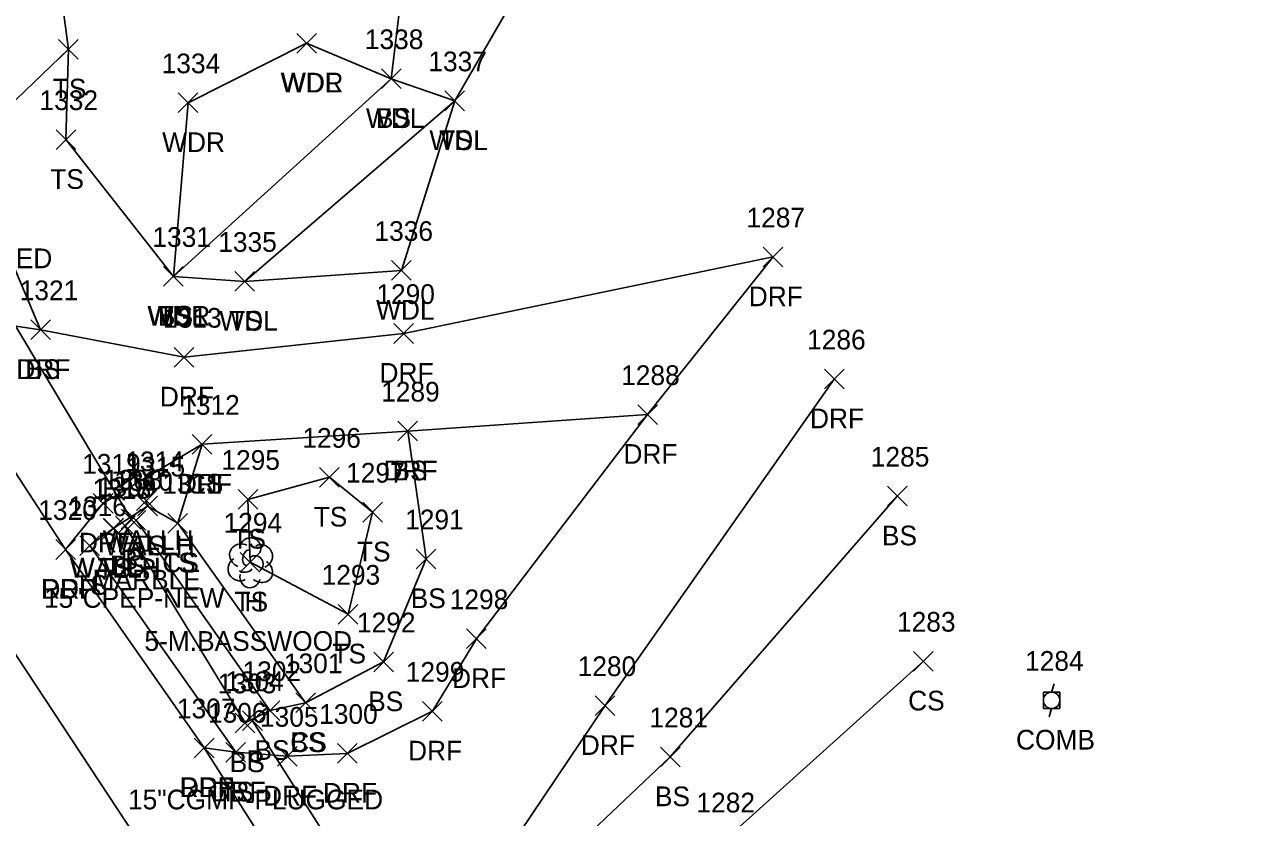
# Model space of a CAD drawing. Extents: x 1501299 to 1502485, y 381423 to 383765.
# Drawn here: x 1501750.2 to 1501874.8, y 383089.7 to 383170.2 of the extents above; entities that cross this region are included whole.
import ezdxf

# ---------------------------------------------------------------- set-up
doc = ezdxf.new("R2010")
doc.units = 0
for name, color, linetype in [('D_A', 7, 'Continuous'), ('D_C', 7, 'Continuous'), ('D_I', 7, 'Continuous'), ('D_TIC', 7, 'Continuous'), ('DCP', 7, 'Continuous'), ('DHW', 7, 'Continuous'), ('L_A', 7, 'Continuous'), ('L_C', 7, 'Continuous'), ('L_I', 7, 'Continuous'), ('L_TIC', 7, 'Continuous'), ('LAWA', 7, 'Continuous'), ('LELB', 7, 'Continuous'), ('LTD', 7, 'Continuous'), ('P_A', 7, 'Continuous'), ('P_I', 7, 'Continuous'), ('P_TIC', 7, 'Continuous'), ('PET', 7, 'Continuous'), ('PRC', 7, 'Continuous'), ('R_A', 7, 'Continuous'), ('R_I', 7, 'Continuous'), ('R_TIC', 7, 'Continuous'), ('RDF', 7, 'Continuous'), ('U_A', 7, 'Continuous'), ('U_I', 7, 'Continuous'), ('UP', 7, 'Continuous')]:
    doc.layers.add(name, color=color, linetype=linetype)

msp = doc.modelspace()

# ---------------------------------------------------------------- linework, layer by layer
at = {"layer": 'D_TIC'}
for points in [[(1501761.59, 383120.84), (1501763.59, 383122.84)], [(1501763.59, 383120.84), (1501761.59, 383122.84)], [(1501761.73, 383120.3), (1501763.73, 383122.3)], [(1501763.73, 383120.3), (1501761.73, 383122.3)], [(1501760.06, 383118.97), (1501762.06, 383120.97)], [(1501762.06, 383118.97), (1501760.06, 383120.97)], [(1501758.24, 383118.02), (1501760.24, 383120.02)], [(1501760.24, 383118.02), (1501758.24, 383120.02)], [(1501758.27, 383118.07), (1501760.27, 383120.07)], [(1501760.27, 383118.07), (1501758.27, 383120.07)], [(1501772.39, 383098.51), (1501774.39, 383100.51)], [(1501774.39, 383098.51), (1501772.39, 383100.51)]]:
    msp.add_lwpolyline(points, dxfattribs=at)
at = {"layer": 'DCP'}
for points in [[(1501761.06, 383119.97), (1501740.36, 383154.45)], [(1501794, 383067.07), (1501773.39, 383099.51)]]:
    msp.add_lwpolyline(points, dxfattribs=at)
at = {"layer": 'DHW'}
msp.add_lwpolyline([(1501762.59, 383121.84), (1501762.73, 383121.3), (1501759.24, 383119.02), (1501759.27, 383119.07)], dxfattribs=at)
at = {"layer": 'L_TIC'}
for points in [[(1501753.69, 383166.68), (1501755.69, 383168.68)], [(1501755.69, 383166.68), (1501753.69, 383168.68)], [(1501753.69, 383166.68), (1501755.69, 383168.68)], [(1501755.69, 383166.68), (1501753.69, 383168.68)], [(1501777.88, 383167.29), (1501779.88, 383169.29)], [(1501779.88, 383167.29), (1501777.88, 383169.29)], [(1501777.88, 383167.29), (1501779.88, 383169.29)], [(1501779.88, 383167.29), (1501777.88, 383169.29)], [(1501786.49, 383163.69), (1501788.49, 383165.69)], [(1501788.49, 383163.69), (1501786.49, 383165.69)], [(1501786.49, 383163.69), (1501788.49, 383165.69)], [(1501788.49, 383163.69), (1501786.49, 383165.69)], [(1501765.85, 383161.24), (1501767.85, 383163.24)], [(1501767.85, 383161.24), (1501765.85, 383163.24)], [(1501792.94, 383161.44), (1501794.94, 383163.44)], [(1501794.94, 383161.44), (1501792.94, 383163.44)], [(1501792.94, 383161.44), (1501794.94, 383163.44)], [(1501794.94, 383161.44), (1501792.94, 383163.44)], [(1501753.44, 383157.5), (1501755.44, 383159.5)], [(1501755.44, 383157.5), (1501753.44, 383159.5)], [(1501787.52, 383144.22), (1501789.52, 383146.22)], [(1501789.52, 383144.22), (1501787.52, 383146.22)], [(1501764.35, 383143.61), (1501766.35, 383145.61)], [(1501766.35, 383143.61), (1501764.35, 383145.61)], [(1501764.35, 383143.61), (1501766.35, 383145.61)], [(1501766.35, 383143.61), (1501764.35, 383145.61)], [(1501764.35, 383143.61), (1501766.35, 383145.61)], [(1501766.35, 383143.61), (1501764.35, 383145.61)], [(1501764.35, 383143.61), (1501766.35, 383145.61)], [(1501766.35, 383143.61), (1501764.35, 383145.61)], [(1501771.6, 383143.11), (1501773.6, 383145.11)], [(1501773.6, 383143.11), (1501771.6, 383145.11)], [(1501771.6, 383143.11), (1501773.6, 383145.11)], [(1501773.6, 383143.11), (1501771.6, 383145.11)], [(1501750.87, 383138.2), (1501752.87, 383140.2)], [(1501752.87, 383138.2), (1501750.87, 383140.2)], [(1501788.16, 383127.91), (1501790.16, 383129.91)], [(1501790.16, 383127.91), (1501788.16, 383129.91)], [(1501767.27, 383126.57), (1501769.27, 383128.57)], [(1501769.27, 383126.57), (1501767.27, 383128.57)], [(1501780.2, 383123.22), (1501782.2, 383125.22)], [(1501782.2, 383123.22), (1501780.2, 383125.22)], [(1501761.73, 383120.3), (1501763.73, 383122.3)], [(1501763.73, 383120.3), (1501761.73, 383122.3)], [(1501771.92, 383120.98), (1501773.92, 383122.98)], [(1501773.92, 383120.98), (1501771.92, 383122.98)], [(1501837.89, 383121.31), (1501839.89, 383123.31)], [(1501839.89, 383121.31), (1501837.89, 383123.31)], [(1501784.59, 383119.68), (1501786.59, 383121.68)], [(1501786.59, 383119.68), (1501784.59, 383121.68)], [(1501784.59, 383119.68), (1501786.59, 383121.68)], [(1501786.59, 383119.68), (1501784.59, 383121.68)], [(1501758.24, 383118.02), (1501760.24, 383120.02)], [(1501760.24, 383118.02), (1501758.24, 383120.02)], [(1501759.46, 383118.27), (1501761.46, 383120.27)], [(1501761.46, 383118.27), (1501759.46, 383120.27)], [(1501760.56, 383118.86), (1501762.56, 383120.86)], [(1501762.56, 383118.86), (1501760.56, 383120.86)], [(1501764.79, 383118.56), (1501766.79, 383120.56)], [(1501766.79, 383118.56), (1501764.79, 383120.56)], [(1501764.79, 383118.56), (1501766.79, 383120.56)], [(1501766.79, 383118.56), (1501764.79, 383120.56)], [(1501755.86, 383116.28), (1501757.86, 383118.28)], [(1501757.86, 383116.28), (1501755.86, 383118.28)], [(1501772.15, 383114.6), (1501774.15, 383116.6)], [(1501774.15, 383114.6), (1501772.15, 383116.6)], [(1501790.02, 383114.94), (1501792.02, 383116.94)], [(1501792.02, 383114.94), (1501790.02, 383116.94)], [(1501782.1, 383109.32), (1501784.1, 383111.32)], [(1501784.1, 383109.32), (1501782.1, 383111.32)], [(1501782.1, 383109.32), (1501784.1, 383111.32)], [(1501784.1, 383109.32), (1501782.1, 383111.32)], [(1501785.7, 383104.48), (1501787.7, 383106.48)], [(1501787.7, 383104.48), (1501785.7, 383106.48)], [(1501840.55, 383104.55), (1501842.55, 383106.55)], [(1501842.55, 383104.55), (1501840.55, 383106.55)], [(1501777.79, 383100.33), (1501779.79, 383102.33)], [(1501779.79, 383100.33), (1501777.79, 383102.33)], [(1501777.79, 383100.33), (1501779.79, 383102.33)], [(1501779.79, 383100.33), (1501777.79, 383102.33)], [(1501774.15, 383099.53), (1501776.15, 383101.53)], [(1501776.15, 383099.53), (1501774.15, 383101.53)], [(1501774.15, 383099.53), (1501776.15, 383101.53)], [(1501776.15, 383099.53), (1501774.15, 383101.53)], [(1501771.63, 383098.29), (1501773.63, 383100.29)], [(1501773.63, 383098.29), (1501771.63, 383100.29)], [(1501770.69, 383095.31), (1501772.69, 383097.31)], [(1501772.69, 383095.31), (1501770.69, 383097.31)], [(1501814.83, 383094.83), (1501816.83, 383096.83)], [(1501816.83, 383094.83), (1501814.83, 383096.83)]]:
    msp.add_lwpolyline(points, dxfattribs=at)
at = {"layer": 'LAWA'}
for points in [[(1501765.35, 383144.61), (1501766.85, 383162.24), (1501778.88, 383168.29)], [(1501765.35, 383144.61), (1501772.6, 383144.11), (1501788.52, 383145.22), (1501793.94, 383162.44), (1501787.49, 383164.69), (1501778.88, 383168.29)]]:
    msp.add_lwpolyline(points, dxfattribs=at)
at = {"layer": 'LELB'}
for points in [[(1501744.07, 383157.49), (1501754.69, 383167.68), (1501752.78, 383182.05), (1501755.19, 383195.99), (1501761.59, 383208.77), (1501771, 383222.88), (1501783.3, 383233.77), (1501801.07, 383247.03), (1501816.32, 383251.23)], [(1501772.6, 383144.11), (1501793.94, 383162.44), (1501805.51, 383182.49), (1501797.96, 383202.01), (1501788.35, 383224.29)], [(1501765.35, 383144.61), (1501787.49, 383164.69), (1501789.31, 383179.79), (1501788.17, 383200.21), (1501778.27, 383209.23)], [(1501765.35, 383144.61), (1501754.44, 383158.5), (1501754.69, 383167.68)], [(1501751.87, 383139.2), (1501744.39, 383156.78)], [(1501789.16, 383128.91), (1501791.02, 383115.94), (1501786.7, 383105.48), (1501778.79, 383101.33), (1501775.15, 383100.53), (1501772.63, 383099.29), (1501760.46, 383119.27)], [(1501778.79, 383101.33), (1501765.79, 383119.56), (1501768.27, 383127.57)], [(1501783.1, 383110.32), (1501773.15, 383115.6), (1501772.92, 383121.98), (1501781.2, 383124.22), (1501785.59, 383120.68)], [(1501869.88, 382950.69), (1501868.77, 382950.2), (1501850.13, 382976.26), (1501827.93, 383012.86), (1501805.25, 383045.65), (1501793.26, 383066.92), (1501794.32, 383067.43), (1501799.89, 383080.74), (1501815.83, 383095.83), (1501838.89, 383122.31)], [(1501765.79, 383119.56), (1501762.73, 383121.3)], [(1501775.15, 383100.53), (1501761.56, 383119.86)], [(1501783.1, 383110.32), (1501785.59, 383120.68)], [(1501771.69, 383096.31), (1501756.86, 383117.28), (1501759.24, 383119.02)], [(1501872.66, 382953.64), (1501855.95, 382979.92), (1501835.17, 383018.01), (1501808.76, 383051.57), (1501808.19, 383064.92), (1501807.02, 383075.45), (1501821.18, 383087.2), (1501841.55, 383105.55)]]:
    msp.add_lwpolyline(points, dxfattribs=at)
at = {"layer": 'LTD'}
msp.add_line((1501773.15, 383115.6), (1501773.15, 383115.6), dxfattribs=at)
msp.add_line((1501773.15, 383115.6), (1501773.15, 383115.6), dxfattribs=at)
msp.add_arc((1501773.19, 383117.03), 1.05, 335.5272, 180.9563, dxfattribs=at)
for centre, major_axis, ratio, start_param, end_param in [((1501772.35, 383116.26), (1.21, -0.51), 0.895232, 1.570796, 4.712389), ((1501774.19, 383116.18), (-1.14, -0.48), 0.949671, 1.570796, 4.712389), ((1501772.06, 383114.89), (0.58, -1.04), 0.959034, 3.141593, 6.283185), ((1501772.94, 383116.05), (-0.208, -0.792), 0.645439, 3.141593, 6.283185), ((1501773.65, 383115.43), (-0.5, 0.667), 0.989748, 3.141593, 6.283185), ((1501772.69, 383114.85), (-0.625, -0.083), 0.423636, 0, 3.141593), ((1501774.15, 383114.76), (-1.09, 0.79), 0.841452, 1.570796, 4.712389), ((1501773.15, 383114.1), (0.26, 1.06), 0.942809, 1.570796, 4.712389)]:
    msp.add_ellipse(centre, major_axis=major_axis, ratio=ratio, start_param=start_param, end_param=end_param, dxfattribs=at)
at = {"layer": 'P_TIC'}
for points in [[(1501753.41, 383115.89), (1501755.41, 383117.89)], [(1501755.41, 383115.89), (1501753.41, 383117.89)], [(1501767.48, 383095.75), (1501769.48, 383097.75)], [(1501769.48, 383095.75), (1501767.48, 383097.75)]]:
    msp.add_lwpolyline(points, dxfattribs=at)
at = {"layer": 'PET'}
msp.add_lwpolyline([(1501787.99, 383066.09), (1501768.48, 383096.75), (1501754.41, 383116.89), (1501736.24, 383144.72), (1501720.75, 383167.97), (1501712.59, 383179.72), (1501694.38, 383207.65), (1501673.6, 383237.52), (1501647.75, 383273.85), (1501633.68, 383294.63), (1501626.39, 383287.88), (1501619.16, 383281.8), (1501626.93, 383271.2), (1501654.42, 383229.17), (1501675.7, 383198.29), (1501696.7, 383166.34)], dxfattribs=at)
at = {"layer": 'PRC'}
msp.add_lwpolyline([(1501960.61, 382718.65), (1501950.96, 382750.48), (1501934.96, 382791.85), (1501913.07, 382836.93), (1501889.31, 382881.38), (1501879.24, 382899.51), (1501856.39, 382940.32), (1501839.67, 382967), (1501816.06, 383004.31), (1501794.78, 383036.25), (1501769.81, 383075.16), (1501745.79, 383111.56), (1501729.43, 383136), (1501711.24, 383163.53), (1501694.82, 383188.2), (1501683.55, 383204), (1501664.64, 383231.24), (1501639.52, 383268.34), (1501626.39, 383287.88)], dxfattribs=at)
at = {"layer": 'R_TIC'}
for points in [[(1501825.27, 383145.59), (1501827.27, 383147.59)], [(1501827.27, 383145.59), (1501825.27, 383147.59)], [(1501825.27, 383145.59), (1501827.27, 383147.59)], [(1501827.27, 383145.59), (1501825.27, 383147.59)], [(1501750.87, 383138.2), (1501752.87, 383140.2)], [(1501752.87, 383138.2), (1501750.87, 383140.2)], [(1501787.75, 383137.82), (1501789.75, 383139.82)], [(1501789.75, 383137.82), (1501787.75, 383139.82)], [(1501765.44, 383135.41), (1501767.44, 383137.41)], [(1501767.44, 383135.41), (1501765.44, 383137.41)], [(1501831.48, 383133.2), (1501833.48, 383135.2)], [(1501833.48, 383133.2), (1501831.48, 383135.2)], [(1501812.53, 383129.59), (1501814.53, 383131.59)], [(1501814.53, 383129.59), (1501812.53, 383131.59)], [(1501812.53, 383129.59), (1501814.53, 383131.59)], [(1501814.53, 383129.59), (1501812.53, 383131.59)], [(1501788.16, 383127.91), (1501790.16, 383129.91)], [(1501790.16, 383127.91), (1501788.16, 383129.91)], [(1501767.27, 383126.57), (1501769.27, 383128.57)], [(1501769.27, 383126.57), (1501767.27, 383128.57)], [(1501757.22, 383120.59), (1501759.22, 383122.59)], [(1501759.22, 383120.59), (1501757.22, 383122.59)], [(1501753.41, 383115.89), (1501755.41, 383117.89)], [(1501755.41, 383115.89), (1501753.41, 383117.89)], [(1501795.13, 383106.83), (1501797.13, 383108.83)], [(1501797.13, 383106.83), (1501795.13, 383108.83)], [(1501790.66, 383099.47), (1501792.66, 383101.47)], [(1501792.66, 383099.47), (1501790.66, 383101.47)], [(1501808.2, 383100.04), (1501810.2, 383102.04)], [(1501810.2, 383100.04), (1501808.2, 383102.04)], [(1501767.48, 383095.75), (1501769.48, 383097.75)], [(1501769.48, 383095.75), (1501767.48, 383097.75)], [(1501770.69, 383095.31), (1501772.69, 383097.31)], [(1501772.69, 383095.31), (1501770.69, 383097.31)], [(1501775.93, 383094.9), (1501777.93, 383096.9)], [(1501777.93, 383094.9), (1501775.93, 383096.9)], [(1501782.02, 383095.19), (1501784.02, 383097.19)], [(1501784.02, 383095.19), (1501782.02, 383097.19)]]:
    msp.add_lwpolyline(points, dxfattribs=at)
at = {"layer": 'RDF'}
for points in [[(1501826.27, 383146.59), (1501788.75, 383138.82), (1501766.44, 383136.41), (1501751.87, 383139.2), (1501746.12, 383140.03), (1501740.61, 383142.67), (1501736.24, 383144.72)], [(1501826.27, 383146.59), (1501813.53, 383130.59), (1501796.13, 383107.83), (1501791.66, 383100.47), (1501783.02, 383096.19), (1501776.93, 383095.9), (1501771.69, 383096.31), (1501768.48, 383096.75)], [(1501787.99, 383066.09), (1501796.83, 383082.64), (1501809.2, 383101.04), (1501832.48, 383134.2)], [(1501813.53, 383130.59), (1501789.16, 383128.91), (1501768.27, 383127.57), (1501758.22, 383121.59), (1501754.41, 383116.89)]]:
    msp.add_lwpolyline(points, dxfattribs=at)
at = {"layer": 'UP'}
for p, q in [((1501853.73, 383100.74), (1501853.73, 383102.41)), ((1501853.73, 383102.41), (1501855.4, 383102.41)), ((1501854.81, 383103.24), (1501854.56, 383102.41)), ((1501855.4, 383102.41), (1501855.4, 383100.74)), ((1501854.56, 383101.58), (1501854.56, 383101.58)), ((1501855.4, 383100.74), (1501853.73, 383100.74)), ((1501854.31, 383099.91), (1501854.56, 383100.74))]:
    msp.add_line(p, q, dxfattribs=at)
msp.add_circle((1501854.56, 383101.58), 0.833, dxfattribs=at)

# ---------------------------------------------------------------- texts
at = {"layer": 'D_A'}
for s, p in [('WALLH', (1501758.18, 383116.84)), ('WALLH', (1501758.32, 383116.3)), ('WALLH', (1501754.83, 383114.02)), ('WALLH', (1501754.86, 383114.07)), ('P', (1501760.44, 383114.97)), ('P', (1501772.77, 383094.51))]:
    msp.add_text(s, height=2, dxfattribs=at).set_placement(p)
at = {"layer": 'D_C'}
for s, p in [('15"CPEP-PLUGGED', (1501727.88, 383145.45)), ('MARBLE', (1501757.14, 383112.84)), ('15"CPEP-NEW', (1501752.21, 383110.97)), ('15"CGMP-PLUGGED', (1501760.74, 383090.51))]:
    msp.add_text(s, height=2, dxfattribs=at).set_placement(p)
at = {"layer": 'D_I'}
for s, p in [('1314', (1501760.47, 383124.84)), ('1315', (1501760.6, 383124.3)), ('1308', (1501758.29, 383122.97)), ('1317', (1501757.12, 383122.02)), ('1318', (1501757.15, 383122.07)), ('1304', (1501770.62, 383102.51))]:
    msp.add_text(s, height=2, dxfattribs=at).set_placement(p)
at = {"layer": 'L_A'}
for s, p in [('TS', (1501753.1, 383162.68)), ('TS', (1501753.1, 383162.68)), ('WDR', (1501776.24, 383163.29)), ('WDL', (1501776.3, 383163.29)), ('WDL', (1501784.91, 383159.69)), ('BS', (1501785.93, 383159.69)), ('WDR', (1501764.21, 383157.24)), ('WDL', (1501791.36, 383157.44)), ('TS', (1501792.35, 383157.44)), ('TS', (1501752.85, 383153.5)), ('WDL', (1501785.94, 383140.22)), ('WDR', (1501762.71, 383139.61)), ('WDL', (1501762.76, 383139.61)), ('TS', (1501763.76, 383139.61)), ('BS', (1501763.79, 383139.61)), ('WDL', (1501770.02, 383139.11)), ('TS', (1501771.01, 383139.11)), ('BS', (1501750.31, 383134.2)), ('BS', (1501787.6, 383123.91)), ('CS', (1501766.71, 383122.57)), ('TS', (1501779.61, 383119.22)), ('TS', (1501771.33, 383116.98)), ('BS', (1501837.33, 383117.31)), ('TS', (1501761.14, 383116.3)), ('TS', (1501784, 383115.68)), ('TS', (1501784, 383115.68)), ('TS', (1501757.65, 383114.02)), ('BS', (1501758.9, 383114.27)), ('BS', (1501760, 383114.86)), ('TS', (1501764.2, 383114.56)), ('CS', (1501764.23, 383114.56)), ('TS', (1501755.27, 383112.28)), ('TS', (1501771.56, 383110.6)), ('H', (1501772.58, 383110.6)), ('BS', (1501789.46, 383110.94)), ('TS', (1501781.51, 383105.32)), ('TS', (1501781.51, 383105.32)), ('BS', (1501785.14, 383100.48)), ('CS', (1501839.99, 383100.55)), ('BS', (1501773.59, 383095.53)), ('BS', (1501773.59, 383095.53)), ('CS', (1501777.23, 383096.33)), ('BS', (1501777.23, 383096.33)), ('BS', (1501771.07, 383094.29)), ('TS', (1501770.1, 383091.31)), ('BS', (1501814.27, 383090.83))]:
    msp.add_text(s, height=2, dxfattribs=at).set_placement(p)
at = {"layer": 'L_C'}
msp.add_text('5-M.BASSWOOD', height=2, dxfattribs=at).set_placement((1501762.41, 383106.6))
at = {"layer": 'L_I'}
for s, p in [('1338', (1501784.8, 383167.69)), ('1338', (1501784.8, 383167.69)), ('1334', (1501764.16, 383165.24)), ('1337', (1501791.25, 383165.44)), ('1337', (1501791.25, 383165.44)), ('1332', (1501751.75, 383161.5)), ('1331', (1501763.22, 383147.61)), ('1331', (1501763.22, 383147.61)), ('1331', (1501763.22, 383147.61)), ('1331', (1501763.22, 383147.61)), ('1336', (1501785.78, 383148.22)), ('1335', (1501769.91, 383147.11)), ('1335', (1501769.91, 383147.11)), ('1321', (1501749.74, 383142.2)), ('1289', (1501786.46, 383131.91)), ('1312', (1501766.15, 383130.57)), ('1296', (1501778.45, 383127.22)), ('1285', (1501836.2, 383125.31)), ('1315', (1501760.6, 383124.3)), ('1295', (1501770.23, 383124.98)), ('1310', (1501759.35, 383122.86)), ('1297', (1501782.9, 383123.68)), ('1297', (1501782.9, 383123.68)), ('1317', (1501757.12, 383122.02)), ('1309', (1501757.68, 383122.27)), ('1311', (1501764.23, 383122.56)), ('1311', (1501764.23, 383122.56)), ('1316', (1501754.68, 383120.28)), ('1291', (1501788.9, 383118.94)), ('1294', (1501770.45, 383118.6)), ('1294', (1501770.45, 383118.6)), ('1293', (1501780.41, 383113.32)), ('1293', (1501780.41, 383113.32)), ('1292', (1501784, 383108.48)), ('1283', (1501838.86, 383108.55)), ('1301', (1501776.58, 383104.33)), ('1301', (1501776.58, 383104.33)), ('1302', (1501772.38, 383103.53)), ('1302', (1501772.38, 383103.53)), ('1303', (1501769.86, 383102.29)), ('1306', (1501768.86, 383099.31)), ('1281', (1501813.71, 383098.83)), ('1282', (1501818.49, 383090.2))]:
    msp.add_text(s, height=2, dxfattribs=at).set_placement(p)
at = {"layer": 'P_A'}
for p in [(1501751.9, 383111.89), (1501765.97, 383091.75)]:
    msp.add_text('RDP', height=2, dxfattribs=at).set_placement(p)
at = {"layer": 'P_I'}
for s, p in [('1320', (1501751.63, 383119.89)), ('1307', (1501765.71, 383099.75))]:
    msp.add_text(s, height=2, dxfattribs=at).set_placement(p)
at = {"layer": 'R_A'}
for p in [(1501823.8, 383141.59), (1501823.8, 383141.59), (1501749.4, 383134.2), (1501786.29, 383133.82), (1501763.98, 383131.41), (1501830.02, 383129.2), (1501811.07, 383125.59), (1501811.07, 383125.59), (1501786.7, 383123.91), (1501765.81, 383122.57), (1501755.76, 383116.59), (1501751.95, 383111.89), (1501793.66, 383102.83), (1501789.19, 383095.47), (1501806.74, 383096.04), (1501766.02, 383091.75), (1501769.22, 383091.31), (1501774.46, 383090.9), (1501780.55, 383091.19)]:
    msp.add_text('DRF', height=2, dxfattribs=at).set_placement(p)
at = {"layer": 'R_I'}
for s, p in [('1287', (1501823.57, 383149.59)), ('1287', (1501823.57, 383149.59)), ('1321', (1501749.74, 383142.2)), ('1290', (1501785.97, 383141.82)), ('1313', (1501764.31, 383139.41)), ('1286', (1501829.73, 383137.2)), ('1288', (1501810.84, 383133.59)), ('1288', (1501810.84, 383133.59)), ('1289', (1501786.46, 383131.91)), ('1312', (1501766.15, 383130.57)), ('1319', (1501756.09, 383124.59)), ('1320', (1501751.63, 383119.89)), ('1298', (1501793.43, 383110.83)), ('1280', (1501806.42, 383104.04)), ('1299', (1501788.96, 383103.47)), ('1307', (1501765.71, 383099.75)), ('1306', (1501768.86, 383099.31)), ('1300', (1501780.16, 383099.19)), ('1305', (1501774.15, 383098.9))]:
    msp.add_text(s, height=2, dxfattribs=at).set_placement(p)
at = {"layer": 'U_A'}
msp.add_text('COMB', height=2, dxfattribs=at).set_placement((1501850.95, 383096.58))
at = {"layer": 'U_I'}
msp.add_text('1284', height=2, dxfattribs=at).set_placement((1501851.87, 383104.58))

doc.saveas('drawing.dxf')
